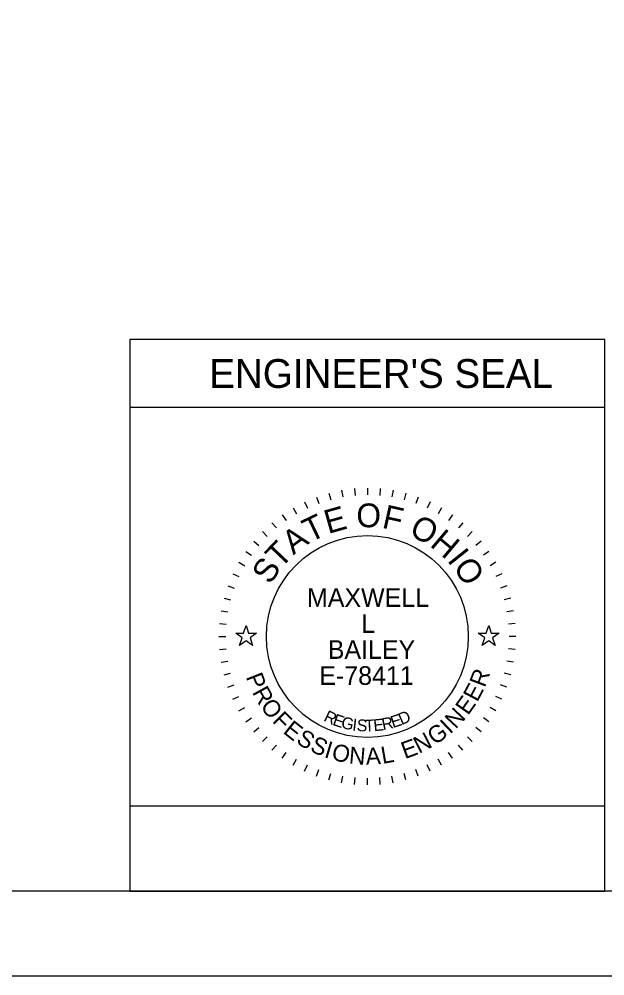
# Model space of a CAD drawing. Extents: x 0 to 44.3, y 0 to 22.
# Drawn here: x 6.7 to 10.15, y 0 to 5.64 of the extents above; entities that cross this region are included whole.
import ezdxf

# ---------------------------------------------------------------- set-up
doc = ezdxf.new("R2010")
doc.units = 0
for name, color, linetype in [('SH_Border', 7, 'Continuous'), ('SH_Cut_Line', 7, 'Continuous'), ('SH_Data', 7, 'Continuous'), ('SH_Seal', 7, 'Continuous')]:
    doc.layers.add(name, color=color, linetype=linetype)

msp = doc.modelspace()

# ---------------------------------------------------------------- linework, layer by layer
at = {"layer": 'SH_Border'}
msp.add_lwpolyline([(1.5, 21.5), (33.5, 21.5), (33.5, 0.5), (1.5, 0.5)], close=True, dxfattribs=at)
at = {"layer": 'SH_Cut_Line'}
msp.add_lwpolyline([(0, 0), (34, 0), (34, 22), (0, 22)], close=True, dxfattribs=at)
at = {"layer": 'SH_Data'}
for p, q in [((10.15, 3.75), (7.35, 3.75)), ((7.35, 3.75), (7.35, 0.5)), ((10.15, 0.5), (10.15, 3.75)), ((10.15, 3.35), (7.35, 3.35)), ((10.15, 0.5), (7.35, 0.5))]:
    msp.add_line(p, q, dxfattribs=at)
msp.add_lwpolyline([(10.15, 0.5), (10.15, 1), (7.35, 1), (7.35, 0.5)], close=True, dxfattribs=at)
at = {"layer": 'SH_Seal'}
for p, q in [((8.4507, 2.8222), (8.4644, 2.7846)), ((8.5235, 2.8452), (8.5339, 2.8065)), ((8.5981, 2.8617), (8.605, 2.8223)), ((8.6737, 2.8717), (8.6772, 2.8318)), ((8.75, 2.875), (8.75, 2.835)), ((8.8263, 2.8717), (8.8228, 2.8318)), ((8.9019, 2.8617), (8.895, 2.8223)), ((8.9765, 2.8452), (8.9661, 2.8065)), ((9.0493, 2.8222), (9.0356, 2.7846)), ((8.3802, 2.793), (8.3971, 2.7568)), ((9.1198, 2.793), (9.1029, 2.7568)), ((8.2481, 2.7168), (8.2711, 2.684)), ((8.3125, 2.7578), (8.3325, 2.7231)), ((9.1875, 2.7578), (9.1675, 2.7231)), ((9.2519, 2.7168), (9.2289, 2.684)), ((8.1876, 2.6703), (8.2133, 2.6396)), ((9.3124, 2.6703), (9.2867, 2.6396)), ((8.1313, 2.6187), (8.1596, 2.5904)), ((9.3687, 2.6187), (9.3404, 2.5904)), ((8.0797, 2.5624), (8.1104, 2.5367)), ((9.4203, 2.5624), (9.3896, 2.5367)), ((8.0332, 2.5019), (8.066, 2.4789)), ((9.4668, 2.5019), (9.434, 2.4789)), ((7.9922, 2.4375), (8.0269, 2.4175)), ((9.5078, 2.4375), (9.4731, 2.4175)), ((7.957, 2.3698), (7.9932, 2.3529)), ((9.543, 2.3698), (9.5068, 2.3529)), ((7.9278, 2.2993), (7.9654, 2.2856)), ((9.5722, 2.2993), (9.5346, 2.2856)), ((7.9048, 2.2265), (7.9435, 2.2161)), ((9.5952, 2.2265), (9.5565, 2.2161)), ((7.8883, 2.1519), (7.9277, 2.145)), ((9.6117, 2.1519), (9.5723, 2.145)), ((7.8783, 2.0763), (7.9182, 2.0728)), ((9.6217, 2.0763), (9.5818, 2.0728)), ((7.875, 2), (7.915, 2)), ((9.625, 2), (9.585, 2)), ((7.8783, 1.9237), (7.9182, 1.9272)), ((9.6217, 1.9237), (9.5818, 1.9272)), ((7.8883, 1.8481), (7.9277, 1.855)), ((9.6117, 1.8481), (9.5723, 1.855)), ((7.9048, 1.7735), (7.9435, 1.7839)), ((9.5952, 1.7735), (9.5565, 1.7839)), ((7.9278, 1.7007), (7.9654, 1.7144)), ((9.5722, 1.7007), (9.5346, 1.7144)), ((7.957, 1.6302), (7.9932, 1.6471)), ((9.543, 1.6302), (9.5068, 1.6471)), ((7.9922, 1.5625), (8.0269, 1.5825)), ((9.5078, 1.5625), (9.4731, 1.5825)), ((8.0332, 1.4981), (8.066, 1.5211)), ((9.4668, 1.4981), (9.434, 1.5211)), ((8.0797, 1.4376), (8.1104, 1.4633)), ((9.4203, 1.4376), (9.3896, 1.4633)), ((8.1313, 1.3813), (8.1596, 1.4096)), ((8.1876, 1.3297), (8.2133, 1.3604)), ((9.3124, 1.3297), (9.2867, 1.3604)), ((9.3687, 1.3813), (9.3404, 1.4096)), ((8.2481, 1.2832), (8.2711, 1.316)), ((9.2519, 1.2832), (9.2289, 1.316)), ((8.3125, 1.2422), (8.3325, 1.2769)), ((8.3802, 1.207), (8.3971, 1.2432)), ((9.1198, 1.207), (9.1029, 1.2432)), ((9.1875, 1.2422), (9.1675, 1.2769)), ((8.4507, 1.1778), (8.4644, 1.2154)), ((8.5235, 1.1548), (8.5339, 1.1935)), ((8.9765, 1.1548), (8.9661, 1.1935)), ((9.0493, 1.1778), (9.0356, 1.2154)), ((8.5981, 1.1383), (8.605, 1.1777)), ((8.6737, 1.1283), (8.6772, 1.1682)), ((8.75, 1.125), (8.75, 1.165)), ((8.8263, 1.1283), (8.8228, 1.1682)), ((8.9019, 1.1383), (8.895, 1.1777))]:
    msp.add_line(p, q, dxfattribs=at)
for points in [[(7.9736, 2.02), (8.0205, 2.02), (8.035, 2.0645), (8.0495, 2.02), (8.0964, 2.02), (8.0585, 1.9924), (8.073, 1.9478), (8.035, 1.9754), (7.997, 1.9478), (8.0115, 1.9924)], [(9.4036, 2.02), (9.4505, 2.02), (9.465, 2.0645), (9.4795, 2.02), (9.5264, 2.02), (9.4885, 1.9924), (9.503, 1.9478), (9.465, 1.9754), (9.427, 1.9478), (9.4415, 1.9924)]]:
    msp.add_lwpolyline(points, close=True, dxfattribs=at)
msp.add_circle((8.75, 2), 0.595, dxfattribs=at)

# ---------------------------------------------------------------- texts
at = {"layer": 'SH_Data'}
msp.add_text("ENGINEER'S SEAL", height=0.17, dxfattribs=at).set_placement((7.8176, 3.465))
at = {"layer": 'SH_Seal'}
for s, height, rotation, p in [('E', 0.14, 15.7571, (8.5184, 2.6038)), ('O', 0.14, 359.7812, (8.6847, 2.6443)), ('F', 0.14, 347.4362, (8.8311, 2.6417)), ('T', 0.14, 25.7167, (8.4116, 2.5518)), ('O', 0.14, 332.2586, (8.9898, 2.6015)), ('A', 0.14, 36.4747, (8.3134, 2.4781)), ('H', 0.14, 319.9136, (9.1132, 2.5361)), ('T', 0.14, 46.4344, (8.2383, 2.3964)), ('I', 0.14, 308.367, (9.2165, 2.4483)), ('S', 0.14, 57.1924, (8.1781, 2.3014)), ('O', 0.14, 303.1491, (9.2521, 2.4089)), ('R', 0.1, 69.2322, (9.4419, 1.6954)), ('P', 0.1, 291.494, (8.0323, 1.7621)), ('R', 0.1, 298.7311, (8.069, 1.6717)), ('E', 0.1, 61.9951, (9.3976, 1.6098)), ('E', 0.1, 54.758, (9.3433, 1.5314)), ('O', 0.1, 306.4666, (8.1155, 1.5883)), ('N', 0.1, 47.0224, (9.2702, 1.4508)), ('F', 0.1, 314.7068, (8.1843, 1.4983)), ('R', 0.07, 334.487, (8.4875, 1.5051)), ('E', 0.07, 341.04, (8.5406, 1.4801)), ('G', 0.07, 347.4752, (8.5914, 1.4618)), ('R', 0.07, 11.9184, (8.8425, 1.4474)), ('E', 0.07, 17.6836, (8.8998, 1.4602)), ('D', 0.07, 23.3052, (8.951, 1.477)), ('E', 0.1, 321.4393, (8.2478, 1.4348)), ('I', 0.07, 353.7858, (8.6591, 1.4468)), ('S', 0.07, 356.8926, (8.6858, 1.4429)), ('T', 0.07, 3.0061, (8.7357, 1.4387)), ('E', 0.07, 6.0117, (8.7889, 1.4412)), ('G', 0.1, 35.0469, (9.1481, 1.357)), ('I', 0.1, 43.287, (9.2368, 1.4214)), ('S', 0.1, 328.6764, (8.3243, 1.3752)), ('N', 0.1, 27.3113, (9.0545, 1.3075)), ('S', 0.1, 335.9134, (8.4064, 1.3266)), ('I', 0.1, 343.1505, (8.4906, 1.2897)), ('O', 0.1, 346.8859, (8.5339, 1.2751)), ('E', 0.1, 20.0742, (8.9712, 1.277)), ('N', 0.1, 355.1261, (8.6388, 1.2517)), ('A', 0.1, 2.8617, (8.7423, 1.2437)), ('L', 0.1, 10.0987, (8.8394, 1.249))]:
    msp.add_text(s, height=height, rotation=rotation, dxfattribs=at).set_placement(p)
for s, p in [('MAXWELL', (8.3941, 2.1749)), ('L', (8.7145, 2.0216)), ('BAILEY', (8.5167, 1.8684)), ('E-78411', (8.4667, 1.7151))]:
    msp.add_text(s, height=0.11, dxfattribs=at).set_placement(p)

doc.saveas('drawing.dxf')
